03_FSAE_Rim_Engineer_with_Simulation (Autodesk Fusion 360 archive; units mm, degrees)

design "03 FSAE Rim - Engineer with Simulation" references "Hexagon Socket Head Cap Screw DIN 912 - M4 x 0.7 x 16 Steel 4.6 Plain", "Hexagon Nut DIN 934 - M4 x 0.7 Steel 6 Plain"
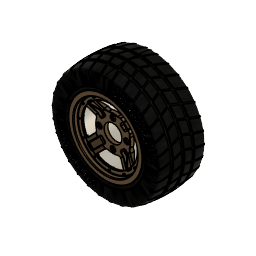
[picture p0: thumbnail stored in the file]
part number: 2026-07-27-09-56-27-671
part number: 2026-08-04-10-59-52-273
part number: 2026-08-04-10-59-52-284
part number: 2026-08-04-10-59-52-289
sketch "Sketch1" plane through (0, 0, 0) normal (1, 0, 0) x axis (0, 1, 0)
  line L1 (153.5, 0) -> (0, 0)
  line L2 (0, 119.5) -> (0, 104)
  line L3 (143.5, 124.5) -> (5, 124.5)
  line L4 (148.5, 134.75) -> (148.5, 129.5)
  line L5 (153.5, 138.25) -> (152, 138.25)
  line L6 (2.5, 119.5) -> (2.5, 104)
  line L7 (143.5, 122) -> (5, 122)
  line L8 (151, 134.75) -> (151, 129.5)
  line L9 (153.5, 135.75) -> (152, 135.75)
  line L10 (2.5, 104) -> (0, 104)
  line L11 (153.5, 135.75) -> (153.5, 138.25)
  arc A1 centre (152, 134.75) radius 3.5 clockwise from (148.5, 134.75) to (152, 138.25)
  arc A2 centre (143.5, 129.5) radius 5 clockwise from (148.5, 129.5) to (143.5, 124.5)
  arc A3 centre (5, 119.5) radius 5 clockwise from (0, 119.5) to (5, 124.5)
  arc A4 centre (5, 119.5) radius 2.5 clockwise from (2.5, 119.5) to (5, 122)
  arc A5 centre (143.5, 129.5) radius 7.5 clockwise from (151, 129.5) to (143.5, 122)
  arc A6 centre (152, 134.75) radius 1 clockwise from (151, 134.75) to (152, 135.75)
  point P1 (0, 0)
  point P2 (0, 0)
  point P4 (0, 104)
  point P3 (153.5, 0)
  point P7 (153.5, 138.25)
  point P6 (148.5, 124.5)
  point P5 (0, 124.5)
  coincident P1 P2
  horizontal L1
  perpendicular L1 L2
  perpendicular L2 L3
  perpendicular L3 L4
  perpendicular L4 L5
  vertical P1 P4
  vertical P3 P7
  tangent L4 A1
  tangent L5 A1
  coincident P6 L3
  coincident P6 L4
  tangent L3 A2
  tangent L4 A2
  coincident P5 L2
  coincident P5 L3
  tangent L2 A3
  tangent L3 A3
  equal A2 A3
  perpendicular L6 L10
  perpendicular L9 L11
  dimension "d1" distance P2 P3 = 153.5
  dimension "d2" = 208
  dimension "d3" = 249
  dimension "d4" = 276.5
  dimension "d5" distance P5 P6 = 148.5
  dimension "d6" radius A1 = 3.5
  dimension "d7" radius A2 = 5
  dimension "d8" = 2.5
revolve "Revolve1" sketch "Sketch1" AlongAngle 360 bodies "FSAE Rim Back"
sketch "Sketch2" plane through (0, 0, 0) normal (0, -1, 0) x axis (1, 0, 0)
  circle C1 centre (0, 0) radius 104
  circle C2 centre (0, 0) radius 119.5
  circle C3 centre (0, 0) radius 112
  circle C4 centre (0, 112) radius 2.15
  point P1 (0, 0)
  point P3 (0, 0)
  point P4 (0, 112)
  coincident P1 P3
  coincident C3 P4
  vertical P3 P4
  dimension "d10" diameter C3 = 224
  dimension "d11" diameter C4 = 4.3
extrude "Extrude1" cut sketch "Sketch2" profile of C4 to an object
circular_pattern "C-Pattern1" TotalAngle 360
canvas "Canvas1"
move "Move1"
sketch "Sketch4" plane through (0, 0, 0) normal (1, 0, 0) x axis (0, 1, 0)
  line L1 (14, 0) -> (0, 0)
  line L2 (14, 72.5) -> (14, 0)
  line L3 (-8, 102.5) -> (14, 72.5)
  line L4 (-8, 124.5) -> (-8, 102.5)
  line L5 (-23.5, 124.5) -> (-8, 124.5)
  line L6 (-23.5, 138) -> (-23.5, 124.5)
  line L7 (-28.25, 138) -> (-23.5, 138)
  line L8 (-28.25, 0) -> (-28.25, 138)
  line L9 (0, 0) -> (-28.25, 0)
  line L10 (-13, 118.1658) -> (-28.25, 119.5)
  line L11 (-13, 102.5) -> (-13, 118.1658)
  line L12 (0, 68.6338) -> (-13, 102.5)
  line L13 (0, 0) -> (0, 68.6338)
  point P1 (0, 0)
  point P2 (0, 0)
  point P11 (0, 0)
  point P12 (-28.25, 119.5)
  point P5 (-8, 102.5)
  point P14 (-13, 102.5)
  point P3 (14, 0)
  point P4 (14, 72.5)
  point P6 (-8, 124.5)
  point P8 (-23.5, 138)
  point P9 (-28.25, 138)
  coincident P1 P2
  horizontal L1
  perpendicular L1 L2
  perpendicular L1 L4
  perpendicular L4 L5
  perpendicular L5 L6
  perpendicular L6 L7
  coincident P1 P11
  collinear L1 L9
  perpendicular L8 L9
  coincident L8 P12
  parallel L8 L11
  vertical L13
  horizontal P5 P14
  dimension "d29" distance P2 P3 = 14
  dimension "d30" = 145
  dimension "d31" = 205
  dimension "d32" = 249
  dimension "d33" = 276
  dimension "d34" distance P4 P6 = 22
  dimension "d35" distance P6 P8 = 15.5
  dimension "d36" distance P8 P9 = 4.75
  dimension "d37" distance L4 L11 = 5
  dimension "d38" angle L12 L13 = 159
  dimension "d39" angle L10 L11 = 95
  dimension "d40" = 239
revolve "Revolve3" sketch "Sketch4" AlongAngle 360 bodies "FSAE Rim Front"
sketch "Sketch5" plane through (0, 0, 0) normal (0, -1, 0) x axis (1, 0, 0)
  circle C1 centre (0, 0) radius 68.6338
  circle C2 centre (0, 0) radius 33
  point P1 (0, 0)
  point P3 (0, 0)
  coincident P1 P3
  dimension "d42" diameter C2 = 66
extrude "Extrude2" cut sketch "Sketch5" profile of C2 to an object
sketch "Sketch6" plane through (0, 0, 0) normal (0, -1, 0) x axis (1, 0, 0)
  circle C1 centre (0, 0) radius 33
  circle C2 centre (0, 0) radius 68.6338
  circle C3 centre (0, 0) radius 50.8
  point P1 (0, 0)
  point P4 (0, 0)
  point P3 (0, 50.8)
  coincident P1 P4
  coincident P3 C3
  vertical P1 P3
  dimension "d45" diameter C3 = 101.6
hole "Hole1" HoleDiameter 10.5 TipAngle 180 CBDepth 5 CBDiameter 20
chamfer "Chamfer2" sketch "Sketch1" distance 0.5
circular_pattern "C-Pattern2" TotalAngle 360
sketch "Sketch7" plane through (0, -13, 0) normal (0, -1, 0) x axis (1, 0, 0)
  circle C1 centre (0, 0) radius 102.5
  circle C2 centre (0, 0) radius 118.1658
  circle C3 centre (0, 0) radius 112
  point P1 (0, 0)
  point P3 (0, 0)
  point P4 (0, 112)
  coincident P1 P3
  coincident C3 P4
  vertical P1 P4
  dimension "d53" diameter C3 = 224
hole "Hole2" HoleDiameter 4.3 TipAngle 180
circular_pattern "C-Pattern3" TotalAngle 360
fillet "Fillet1" radius 1 3 2
chamfer "Chamfer1" distance 0.5
form "Form1" bodies "Tire"
fillet "Fillet2" radius 5
sketch "Sketch8" plane through (0, 0, 0) normal (1, 0, 0) x axis (0, 1, 0)
  line L1 (47.5, 224.911) -> (47.5, 204.911)
  line L2 (57.5, 224.911) -> (47.5, 224.911)
  line L3 (57.5, 204.9943) -> (57.5, 224.911)
  line L4 (87.5, 224.911) -> (87.5, 204.2438)
  line L5 (97.5, 224.911) -> (87.5, 224.911)
  line L6 (97.5, 203.6595) -> (97.5, 224.911)
  line L7 (17.5, 224.911) -> (17.5, 203.6595)
  line L8 (7.5, 224.911) -> (17.5, 224.911)
  line L9 (7.5, 202.9073) -> (7.5, 224.911)
  arc A1 centre (57.5, -395.0057) radius 600 clockwise from (-46, 196) to (161, 196)
  point P2 (-46, 196)
  point P3 (161, 196)
  point P8 (57.5, 204.9943)
  point P9 (87.5, 204.2438)
  point P12 (97.5, 203.6595)
  point P13 (17.5, 203.6595)
  point P16 (7.5, 202.9073)
  point P5 (47.5, 204.911)
  point P1 (0, 0)
  point P6 (47.5, 224.911)
  point P7 (57.5, 224.911)
  horizontal P2 P3
  vertical L1
  perpendicular L1 L2
  midpoint A1 P8
  perpendicular L2 L3
  coincident A1 P9
  parallel L3 L4
  perpendicular L4 L5
  coincident A1 P12
  perpendicular L5 L6
  coincident A1 P13
  perpendicular L5 L7
  perpendicular L7 L8
  coincident A1 P16
  perpendicular L8 L9
  collinear L2 L8
  collinear L2 L5
  equal L2 L8
  equal L2 L5
  coincident A1 P5
  dimension "d68" radius A1 = 600
  dimension "d69" distance P1 P3 = 196
  dimension "d70" distance P1 P2 = 46
  dimension "d71" distance P1 P3 = 161
  dimension "d73" distance P6 P7 = 10
  dimension "d74" distance L1 L7 = 30
  dimension "d75" distance L3 L4 = 30
  dimension "d76" distance P5 P6 = 20
revolve "Revolve4" AlongAngle 360
revolve "Revolve5" sketch "Sketch8" AlongAngle 360
work_plane "WorkPlane1" AlongDistance 275 ExtraOffset 0
sketch "Sketch9" plane through (0, 0, 275) normal (0, 0, 1) x axis (1, 0, 0)
  line L1 (-48.7008, 53.5011) -> (0, -75.7953)
  line L2 (0, 197.5142) -> (-48.7008, 53.5011)
  line L3 (-43.392, 53.5917) -> (4.6791, -74.0329)
  line L4 (4.7365, 195.9124) -> (-43.392, 53.5917)
  line L5 (4.6791, -74.0329) -> (0, -75.7953)
  line L6 (0, 197.5142) -> (4.7365, 195.9124)
  perpendicular L3 L5
  perpendicular L2 L6
  dimension "d80" = 5
step "SurfaceExtend" extendDistance 125
extrude "Extrude3" cut sketch "Sketch9" to an object
circular_pattern "C-Pattern4" countU 30 TotalAngle 360
remove_body "RemoveBody1"
remove_body "RemoveBody2"
work_plane "WorkPlane2" AlongDistance -150 ExtraOffset 0
sketch "Sketch10" plane through (0, -150, 0) normal (0, 1, 0) x axis (1, 0, 0)
  circle C1 centre (0, 0) radius 157.5
  point P1 (0, 0)
  point P2 (0, 0)
  coincident P1 P2
  dimension "d88" diameter C1 = 315
  dimension "d89" Text1-Height = 20
extrude "Extrude4" sketch "Sketch10" blind 2
circular_pattern "C-Pattern5" TotalAngle 360
component_from_bodies "Body->Comp1"
component_from_bodies "Body->Comp2"
component_from_bodies "Body->Comp3"
sketch "Sketch1" plane through (0, -13, 0) normal (0, -1, 0) x axis (1, 0, 0)
  line L1 (0, 103.056) -> (0, 0)
  line L2 (103.056, 0) -> (0, 0)
  line L3 (72.8716, 72.8716) -> (0, 0)
  line L4 (88.3726, 53.0172) -> (60.1041, 24.7487)
  line L5 (53.0172, 88.3726) -> (24.7487, 60.1041)
  circle C1 centre (0, 0) radius 103.056
  circle C2 centre (0, 112) radius 2.15
  circle C3 centre (56, 96.9948) radius 2.15
  circle C4 centre (96.9948, 56) radius 2.15
  circle C5 centre (112, 0) radius 2.15
  circle C6 centre (96.9948, -56) radius 2.15
  circle C7 centre (56, -96.9948) radius 2.15
  circle C8 centre (0, -112) radius 2.15
  circle C9 centre (-56, -96.9948) radius 2.15
  circle C10 centre (-96.9948, -56) radius 2.15
  circle C11 centre (-112, 0) radius 2.15
  circle C12 centre (-96.9948, 56) radius 2.15
  circle C13 centre (-56, 96.9948) radius 2.15
  circle C14 centre (0, 0) radius 116.3331
  arc A1 centre (0, 0) radius 65 clockwise from (0, 65) to (65, 0)
  arc A2 centre (0, 0) radius 65 clockwise from (65, 0) to (0, 65)
  point P2 (0, 0)
  point P16 (0, 0)
  point P17 (0, 103.056)
  point P18 (103.056, 0)
  point P15 (0, 0)
  point P19 (0, 0)
  point P20 (72.8716, 72.8716)
  point P22 (24.7487, 60.1041)
  point P21 (60.1041, 24.7487)
  point P23 (53.0172, 88.3726)
  point P24 (88.3726, 53.0172)
  point P25 (0, 65)
  point P26 (65, 0)
  concentric C1 A1
  coincident P2 P16
  coincident C1 P17
  vertical L1
  coincident C1 P18
  perpendicular L1 L2
  coincident P15 P19
  coincident C1 P20
  coincident P22 A1
  coincident P21 A1
  coincident C1 P23
  coincident C1 P24
  coincident L1 P25
  coincident L2 P26
  concentric A1 A2
  dimension "d95" diameter A1 = 130
  dimension "d96" angle L1 L3 = 45
extrude "Extrude1" cut sketch "Sketch1" profile of C1 L1 L2 L4 L5 A1 to an object
circular_pattern "C-Pattern1" TotalAngle 360
sketch "Sketch2" plane through (0, -13, 0) normal (0, -1, 0) x axis (1, 0, 0)
  line L1 (72.8716, 72.8716) -> (0, 0)
  line L2 (65.9862, 82.9568) -> (25.8367, 42.8073)
  line L3 (82.9568, 65.9862) -> (42.8073, 25.8367)
  arc A1 centre (0, 0) radius 103.056 clockwise from (-53.0172, 88.3726) to (53.0172, 88.3726)
  arc A2 centre (0, 0) radius 103.056 clockwise from (53.0172, 88.3726) to (88.3726, 53.0172)
  arc A3 centre (0, 0) radius 103.056 clockwise from (88.3726, 53.0172) to (88.3726, -53.0172)
  arc A4 centre (0, 0) radius 103.056 clockwise from (88.3726, -53.0172) to (53.0172, -88.3726)
  arc A5 centre (0, 0) radius 103.056 clockwise from (53.0172, -88.3726) to (-53.0172, -88.3726)
  arc A6 centre (0, 0) radius 103.056 clockwise from (-53.0172, -88.3726) to (-88.3726, -53.0172)
  arc A7 centre (0, 0) radius 103.056 clockwise from (-88.3726, -53.0172) to (-88.3726, 53.0172)
  arc A8 centre (0, 0) radius 103.056 clockwise from (-88.3726, 53.0172) to (-53.0172, 88.3726)
  circle C1 centre (0, 112) radius 2.15
  circle C2 centre (56, 96.9948) radius 2.15
  circle C3 centre (96.9948, 56) radius 2.15
  circle C4 centre (112, 0) radius 2.15
  circle C5 centre (96.9948, -56) radius 2.15
  circle C6 centre (56, -96.9948) radius 2.15
  circle C7 centre (0, -112) radius 2.15
  circle C8 centre (-56, -96.9948) radius 2.15
  circle C9 centre (-96.9948, -56) radius 2.15
  circle C10 centre (-112, 0) radius 2.15
  circle C11 centre (-96.9948, 56) radius 2.15
  circle C12 centre (-56, 96.9948) radius 2.15
  circle C13 centre (0, 0) radius 116.3331
  circle C14 centre (0, 0) radius 50
  circle C15 centre (0, 0) radius 106
  point P23 (0, 0)
  point P25 (0, 0)
  point P27 (25.8367, 42.8073)
  point P28 (42.8073, 25.8367)
  point P29 (82.9568, 65.9862)
  point P30 (65.9862, 82.9568)
  parallel L1 L2
  parallel L1 L3
  coincident P23 P25
  concentric C14 C15
  coincident C14 P27
  coincident C14 P28
  coincident C15 P29
  coincident C15 P30
  dimension "d103" distance L1 L2 = 12
  dimension "d104" distance L1 L3 = 12 (= "d103")
  dimension "d105" diameter C14 = 100
  dimension "d106" diameter C15 = 212
extrude "Extrude2" cut sketch "Sketch2" profile of A2 L2 L3 C14 C15 to an object offset 2
fillet "Fillet1" radius 5
fillet "Fillet2" radius 10
fillet "Fillet3" radius 2
circular_pattern "C-Pattern2" TotalAngle 360
fillet "Fillet4" radius 15 5
chamfer "Chamfer1" sketch "Sketch1" distance 1
step "Screw1"
joint "Assemble" alignAngle 0 alignOffsetX 0 alignOffsetY 0 alignOffsetZ 0
step "Screw2"
joint "Assemble" alignAngle 0 alignOffsetX 0 alignOffsetY 0 alignOffsetZ 0
step "Screw3"
joint "Assemble" alignAngle 0 alignOffsetX 0 alignOffsetY 0 alignOffsetZ 0
step "Screw4"
joint "Assemble" alignAngle 0 alignOffsetX 0 alignOffsetY 0 alignOffsetZ 0
step "Screw5"
joint "Assemble" alignAngle 0 alignOffsetX 0 alignOffsetY 0 alignOffsetZ 0
step "Screw6"
joint "Assemble" alignAngle 0 alignOffsetX 0 alignOffsetY 0 alignOffsetZ 0
step "Screw7"
joint "Assemble" alignAngle 0 alignOffsetX 0 alignOffsetY 0 alignOffsetZ 0
step "Screw8"
joint "Assemble" alignAngle 0 alignOffsetX 0 alignOffsetY 0 alignOffsetZ 0
step "Screw9"
joint "Assemble" alignAngle 0 alignOffsetX 0 alignOffsetY 0 alignOffsetZ 0
step "Screw10"
joint "Assemble" alignAngle 0 alignOffsetX 0 alignOffsetY 0 alignOffsetZ 0
step "Screw11"
joint "Assemble" alignAngle 0 alignOffsetX 0 alignOffsetY 0 alignOffsetZ 0
step "Screw12"
joint "Assemble" alignAngle 0 alignOffsetX 0 alignOffsetY 0 alignOffsetZ 0
step "Nut13"
joint "Assemble" alignAngle 0 alignOffsetX 0 alignOffsetY 0 alignOffsetZ 0
step "Nut14"
joint "Assemble" alignAngle 0 alignOffsetX 0 alignOffsetY 0 alignOffsetZ 0
step "Nut15"
joint "Assemble" alignAngle 0 alignOffsetX 0 alignOffsetY 0 alignOffsetZ 0
step "Nut16"
joint "Assemble" alignAngle 0 alignOffsetX 0 alignOffsetY 0 alignOffsetZ 0
step "Nut17"
joint "Assemble" alignAngle 0 alignOffsetX 0 alignOffsetY 0 alignOffsetZ 0
step "Nut18"
joint "Assemble" alignAngle 0 alignOffsetX 0 alignOffsetY 0 alignOffsetZ 0
step "Nut19"
joint "Assemble" alignAngle 0 alignOffsetX 0 alignOffsetY 0 alignOffsetZ 0
step "Nut20"
joint "Assemble" alignAngle 0 alignOffsetX 0 alignOffsetY 0 alignOffsetZ 0
step "Nut21"
joint "Assemble" alignAngle 0 alignOffsetX 0 alignOffsetY 0 alignOffsetZ 0
step "Nut22"
joint "Assemble" alignAngle 0 alignOffsetX 0 alignOffsetY 0 alignOffsetZ 0
step "Nut23"
joint "Assemble" alignAngle 0 alignOffsetX 0 alignOffsetY 0 alignOffsetZ 0
step "Nut24"
joint "Assemble" alignAngle 0 alignOffsetX 0 alignOffsetY 0 alignOffsetZ 0
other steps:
base_feature "Base Feature1" bodies "FSAE Rim Back"
base_feature "Base Feature1" bodies "Tire"
base_feature "Base Feature1" bodies "FSAE Rim Front"
create_component "CreateComponent1"
reparent_decal "ReparentDecal1"
remove_body "RemoveBody3"
create_component "CreateComponent2"
reparent_decal "ReparentDecal2"
remove_body "RemoveBody4"
create_component "CreateComponent3"
reparent_decal "ReparentDecal3"
remove_body "RemoveBody5"
joint_origin "JointOrigin1"
joint_origin "JointOrigin2"
joint_origin "JointOrigin3"
joint_origin "JointOrigin4"
joint_origin "JointOrigin5"
joint_origin "JointOrigin6"
joint_origin "JointOrigin7"
joint_origin "JointOrigin8"
joint_origin "JointOrigin9"
joint_origin "JointOrigin10"
joint_origin "JointOrigin11"
joint_origin "JointOrigin12"
joint_origin "JointOrigin1"
joint_origin "JointOrigin2"
joint_origin "JointOrigin3"
joint_origin "JointOrigin4"
joint_origin "JointOrigin5"
joint_origin "JointOrigin6"
joint_origin "JointOrigin7"
joint_origin "JointOrigin8"
joint_origin "JointOrigin9"
joint_origin "JointOrigin10"
joint_origin "JointOrigin11"
joint_origin "JointOrigin12"
named bodies: "FSAE Rim Back", "FSAE Rim Front", "Tire"

design "Hexagon Nut DIN 934 - M4 x 0.7 Steel 6 Plain"
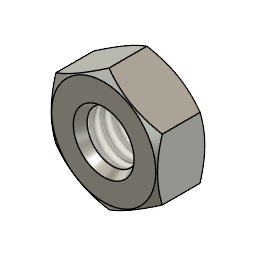
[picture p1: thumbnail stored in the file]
description: Hexagon Nut DIN 934 - M4 x 0.7
part number: DIN 934 - M4 x 0.7 Steel 6 Plain
parameter "adsk_nheig" = 3.2
parameter "adsk_maxdia" = 8.085
parameter "adsk_nomdia" = 4
parameter "adsk_waflat" = 7
parameter "adsk_chamang1" = 30
parameter "adsk_chamang2" = 30
parameter "adsk_beardia" = 6.86 (= "adsk_waflat * 0.98")
sketch "Sketch1" plane through (0, 0, 0) normal (0, 1, 0) x axis (1, 0, 0)
  line L1 (0, -3.2) -> (0, 0)
  line L2 (-3.43, 0) -> (-2, 0)
  line L3 (-4.0425, -0.3536) -> (-3.43, 0)
  line L4 (-4.0425, -2.8464) -> (-4.0425, -0.3536)
  line L5 (-3.43, -3.2) -> (-4.0425, -2.8464)
  line L6 (-2, -3.2) -> (-3.43, -3.2)
  line L7 (-2, 0) -> (-2, -3.2)
  point P3 (0, -3.2)
  point P1 (0, 0)
  point P2 (0, 0)
  point P10 (0, 0)
  point P5 (-3.43, 0)
  point P8 (-3.43, -3.2)
  vertical L1
  coincident L1 P3
  coincident P1 L1
  horizontal L2
  coincident P1 L2
  coincident P2 P10
  coincident P3 L6
  vertical P5 P8
  dimension "d121" = 4 (= "adsk_nomdia")
  dimension "d122" angle L2 L3 = 30 (= "adsk_chamang1")
  dimension "d123" angle L5 L6 = 30 (= "adsk_chamang2")
  dimension "d128" = 8.085 (= "adsk_maxdia")
  dimension "d172" = 6.86 (= "adsk_beardia")
  dimension "d179" distance L2 L6 = 3.2 (= "adsk_nheig")
revolve "Revolve1" sketch "Sketch1" AlongAngle 360
sketch "Sketch8" plane through (0, 0, 3.2) normal (0, 0, 1) x axis (1, 0, 0)
  line L1 (-3.5, 2.0228) -> (-3.5, -2.0228)
  circle C1 centre (0, 0) radius 2
  circle C2 centre (0, 0) radius 4.0425
  point P3 (-3.5, 2.0228)
  point P2 (-3.5, -2.0228)
  point P1 (0, 0)
  coincident P3 C2
  coincident P2 C2
  vertical L1
  dimension "d114" distance P1 L1 = 3.5 (= "adsk_waflat / 2")
extrude "Extrude5" cut sketch "Sketch8" profile of L1 C2 no distance stored
circular_pattern "C-Pattern2" TotalAngle 360
thread "Thread3" ThreadOffset 0 ThreadLength 10
sketch "Sketch12" plane through (0, 0, 0) normal (0, 1, 0) x axis (1, 0, 0)
  line L1 (0, 0) -> (-2, 0)
  line L2 (-2, 0) -> (-1.0762, -1.6)
  line L3 (0, -3.2) -> (-2, -3.2)
  line L4 (-2, -3.2) -> (-1.0762, -1.6)
  line L5 (0, -3.2) -> (0, 0)
  point P4 (-1.0762, -1.6)
  point P7 (-1.0762, -1.6)
  point P2 (-2, 0)
  point P5 (-2, -3.2)
  point P6 (0, -3.2)
  point P9 (0, -3.2)
  point P1 (0, 0)
  point P3 (0, 0)
  horizontal L1
  coincident P4 P7
  vertical P2 P5
  coincident P6 P9
  coincident P1 P3
  perpendicular L3 L5
  dimension "d169" angle L3 L4 = 60
  dimension "d177" distance P2 L5 = 2 (= "adsk_nomdia * 0.5")
  dimension "d178" angle L1 L2 = 60
revolve "Revolve3" sketch "Sketch12" AlongAngle 360
joint_origin "JointOrigin9" OffsetX 0 OffsetY 0 OffsetZ 0 AngleZ 0
joint_origin "JointOrigin10" OffsetX 0 OffsetY 0 OffsetZ 3.2 (= "adsk_nheig") AngleZ 0

design "Hexagon Socket Head Cap Screw DIN 912 - M4 x 0.7 x 16 Steel 4.6 Plain"
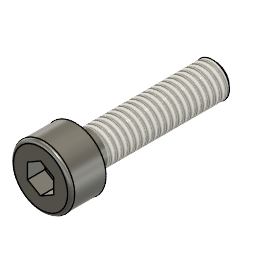
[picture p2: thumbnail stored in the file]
description: Hexagon Socket Head Cap Screw DIN 912 - M4 x 0.7 x 16
part number: DIN 912 - M4 x 0.7 x 16 Steel 4.6 Plain
parameter "adsk_nomlen" = 16
parameter "adsk_headh" = 4
parameter "adsk_headdia" = 7
parameter "adsk_nomdia" = 4
parameter "adsk_philwidth" = 3
parameter "adsk_phildepth" = 2
parameter "adsk_thrlen" = 14.25
parameter "adsk_startlen" = 0.4294
parameter "adsk_endpointdia" = 3.1412
sketch "Sketch1" plane through (0, 0, 0) normal (0, 1, 0) x axis (1, 0, 0)
  line L1 (-2, 16) -> (-2, 0)
  line L2 (0, 16) -> (-2, 16)
  line L3 (0, -4) -> (0, 16)
  line L4 (-3.5, 0) -> (-2, 0)
  line L5 (-3.5, -4) -> (-3.5, 0)
  line L6 (0, -4) -> (-3.5, -4)
  point P1 (0, 0)
  point P4 (0, 16)
  point P7 (0, -4)
  point P5 (-3.5, 0)
  perpendicular L1 L2
  collinear P1 P4 P7
  perpendicular L1 L4
  coincident P1 L4
  vertical L3
  coincident L3 P7
  perpendicular L3 L6
  dimension "d101" distance P1 L2 = 16 (= "adsk_nomlen")
  dimension "d102" distance P5 L6 = 4 (= "adsk_headh")
  dimension "d109" = 7 (= "adsk_headdia")
  dimension "d110" = 4 (= "adsk_nomdia")
revolve "Revolve1" sketch "Sketch1" AlongAngle 360
work_plane "WorkPlane1" AlongDistance 4 (= "adsk_headh")
sketch "Sketch6" plane through (0, 0, 4) normal (0, 0, 1) x axis (1, 0, 0)
  line L1 (1.5, -0.866) -> (0, -1.7321)
  line L2 (1.5, 0.866) -> (1.5, -0.866)
  line L3 (0, 1.7321) -> (1.5, 0.866)
  line L4 (-1.5, 0.866) -> (0, 1.7321)
  line L5 (-1.5, -0.866) -> (-1.5, 0.866)
  line L6 (0, -1.7321) -> (-1.5, -0.866)
  point P1 (0, 0)
  point P8 (0, 0)
  coincident P1 P8
  vertical L2
  dimension "d111" distance L2 L5 = 3 (= "adsk_philwidth")
extrude "Extrude1" cut sketch "Sketch6" no distance stored
extrude "Extrude2" cut of existing geometry no distance stored taper -85
thread "Thread3" ThreadOffset 0 ThreadLength 14.25 (= "min(adsk_thrlen; adsk_nomlen - 0.001 mm)")
fillet "Fillet4" radius 0.4 (= "adsk_nomdia * 0.1")
sketch "Sketch7" plane through (0, 0, 0) normal (0, 1, 0) x axis (1, 0, 0)
  line L1 (-2.04, 15.5706) -> (-2.04, 16)
  line L2 (-1.5706, 16) -> (-2.04, 15.5706)
  line L3 (0, -4) -> (0, 16)
  line L4 (0, 16) -> (-2.04, 16)
  point P5 (0, 16)
  point P7 (0, 16)
  point P4 (-1.5706, 16)
  point P3 (-2.04, 15.5706)
  coincident P5 P7
  perpendicular L3 L4
  coincident P4 L4
  perpendicular L1 L4
  dimension "d104" distance P4 L3 = 1.5706 (= "adsk_endpointdia / 2")
  dimension "d105" distance L1 P7 = 2.04 (= "adsk_nomdia * 0.51")
  dimension "d106" distance P3 L4 = 0.4294 (= "adsk_startlen")
revolve "Revolve3" sketch "Sketch7" AlongAngle 360
joint_origin "JointOrigin2" OffsetX 0 OffsetY 0 OffsetZ 0 AngleZ 0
